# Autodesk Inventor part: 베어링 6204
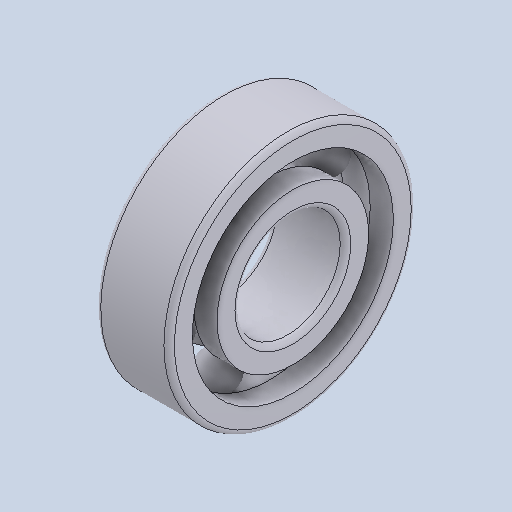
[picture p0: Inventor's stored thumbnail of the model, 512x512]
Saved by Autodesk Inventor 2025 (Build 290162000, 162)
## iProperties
Created: 2025-08
Part Number: 베어링 6204
Material: 강철, 연강
Description: 깊은 그루브 볼 베어링
Document SubType Name: Modeling
Designer: infra02
Density: 7.86 g/cm^3
Appearance: 기본값
Author: jhkim
Sending System: Autodesk Inventor 2026
Preprocessor: ST-DEVELOPER v20.1
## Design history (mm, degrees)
feature "Solid1"
feature "Solid1:1"
feature "Solid1:2"
feature "Solid1:3"
feature "Solid1:4"
feature "Solid1:5"
feature "Solid1:6"
feature "Solid1:7"
feature "Solid1:8"
node "솔리드1"
node "솔리드2"
node "솔리드3"
node "솔리드4"
node "솔리드5"
node "솔리드6"
node "솔리드7"
node "솔리드8"
node "솔리드9"
